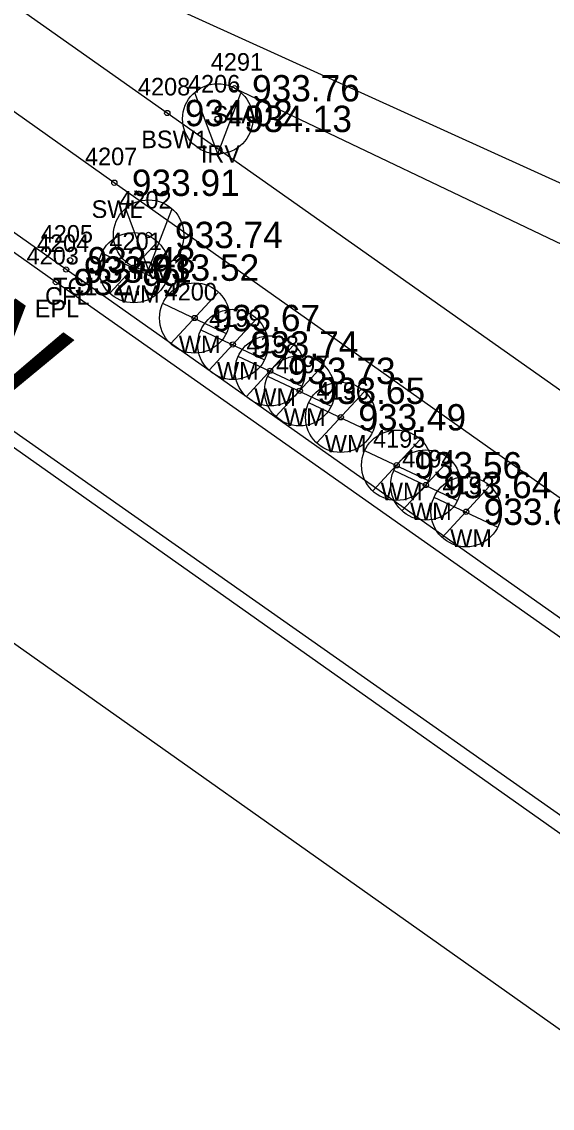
# Model space of a CAD drawing. Extents: x 1575382 to 1578175, y 1099175 to 1101955.
# Drawn here: x 1577254.7 to 1577284.9, y 1101338.2 to 1101400.1 of the extents above; entities that cross this region are included whole.
import ezdxf

# ---------------------------------------------------------------- set-up
doc = ezdxf.new("R2010")
doc.units = 0
for name, color, linetype in [('RD_EX_Bldg', 7, 'Continuous'), ('RD_EX_BldgApp', 7, 'Continuous'), ('RD_EX_Conc', 7, 'Continuous'), ('RD_EX_Conc_txCode', 7, 'Continuous'), ('RD_EX_Misc_txCode', 7, 'Continuous'), ('RD_EX_Road', 7, 'Continuous'), ('RD_EX_Road_txCode', 7, 'Continuous'), ('RD_EX_TX_Conc_ELEV', 7, 'Continuous'), ('RD_EX_TX_Misc_ELEV', 7, 'Continuous'), ('RD_EX_TX_Road_ELEV', 7, 'Continuous'), ('RD_EX_TX_UT_ELEV', 7, 'Continuous'), ('RD_EX_TX_VEG_ELEV', 7, 'Continuous'), ('RD_EX_UT', 7, 'Continuous'), ('RD_EX_UT_txCode', 7, 'Continuous'), ('RD_EX_VEG', 7, 'Continuous'), ('RD_EX_VEG_txCode', 7, 'Continuous'), ('RD_HC_Cl', 7, 'Continuous'), ('RD_HC_Data', 7, 'Continuous'), ('RD_SMD_Locator', 7, 'Continuous')]:
    doc.layers.add(name, color=color, linetype=linetype)

msp = doc.modelspace()

# ---------------------------------------------------------------- linework, layer by layer
at = {"layer": 'RD_EX_Bldg'}
msp.add_lwpolyline([(1577241.109, 1101410.992), (1577311.945, 1101378.805), (1577394.954, 1101563.591), (1577324.118, 1101595.777), (1577241.109, 1101410.992)], dxfattribs=at)
at = {"layer": 'RD_EX_BldgApp'}
for p, q in [((1577265.827, 1101392.566), (1577264.524, 1101396.049)), ((1577265.827, 1101392.566), (1577267.15, 1101396.012)), ((1577261.895, 1101385.958), (1577260.591, 1101389.441)), ((1577261.895, 1101385.958), (1577263.217, 1101389.403))]:
    msp.add_line(p, q, dxfattribs=at)
for centre, radius in [((1577265.827, 1101394.559), 2), ((1577265.827, 1101394.559), 0.15), ((1577261.895, 1101387.951), 2), ((1577261.895, 1101387.951), 0.15)]:
    msp.add_circle(centre, radius, dxfattribs=at)
at = {"layer": 'RD_EX_Conc'}
for points in [[(1577326.739, 1101405.232), (1577316.348, 1101381.047), (1577314.702, 1101377.446), (1577312.765, 1101373.034), (1577307.574, 1101368.224), (1577302.647, 1101367.838), (1577295.881, 1101371.65), (1577262.958, 1101394.891), (1577234.439, 1101415.011), (1577222.087, 1101423.725), (1577202.935, 1101437.614), (1577200.917, 1101438.921), (1577194.112, 1101443.955), (1577177.581, 1101455.534), (1577173.583, 1101458.393), (1577156.819, 1101470.205), (1577152.82, 1101472.9), (1577143.368, 1101479.788), (1577139.034, 1101482.935)], [(1577305.91, 1101358.397), (1577259.945, 1101390.922), (1577231.605, 1101411.039), (1577219.425, 1101419.77), (1577221.243, 1101412.218)], [(1577306.229, 1101358.147), (1577304.05, 1101352.897), (1577257.209, 1101385.982), (1577216.103, 1101415.107)]]:
    msp.add_lwpolyline(points, dxfattribs=at)
at = {"layer": 'RD_EX_Road'}
for points in [[(1577350.994, 1101394.654), (1577333.617, 1101354.382), (1577330.309, 1101348.321), (1577323.84, 1101345.402), (1577317.431, 1101344.498), (1577311.613, 1101346.411), (1577303.255, 1101352.397), (1577256.622, 1101385.271), (1577215.6, 1101414.322), (1577175.525, 1101442.942), (1577135.202, 1101471.708)], [(1577206.431, 1101064.716), (1577225.664, 1101106.496), (1577239.191, 1101137.5), (1577259.229, 1101183.338), (1577279.151, 1101229.325), (1577299.025, 1101275.068), (1577314.414, 1101310.726), (1577314.923, 1101317.44), (1577309.623, 1101326.254), (1577295.813, 1101333.968), (1577286.609, 1101341.784), (1577246.231, 1101370.35), (1577205.316, 1101399.097), (1577164.905, 1101427.552), (1577123.312, 1101456.71)]]:
    msp.add_lwpolyline(points, dxfattribs=at)
at = {"layer": 'RD_EX_UT'}
for p, q in [((1577259.699, 1101384.632), (1577262.366, 1101387.528)), ((1577259.217, 1101386.927), (1577262.848, 1101385.214)), ((1577263.163, 1101381.764), (1577265.83, 1101384.661)), ((1577262.682, 1101384.06), (1577266.312, 1101382.347)), ((1577265.338, 1101380.262), (1577268.005, 1101383.159)), ((1577264.857, 1101382.557), (1577268.487, 1101380.845)), ((1577267.46, 1101378.759), (1577270.127, 1101381.656)), ((1577266.978, 1101381.055), (1577270.609, 1101379.342)), ((1577269.139, 1101377.623), (1577271.806, 1101380.52)), ((1577268.658, 1101379.919), (1577272.288, 1101378.206)), ((1577271.471, 1101376.115), (1577274.139, 1101379.012)), ((1577270.99, 1101378.41), (1577274.621, 1101376.698)), ((1577274.656, 1101373.385), (1577277.323, 1101376.282)), ((1577274.174, 1101375.681), (1577277.805, 1101373.968)), ((1577276.318, 1101372.26), (1577278.985, 1101375.157)), ((1577275.836, 1101374.555), (1577279.467, 1101372.843)), ((1577278.604, 1101370.739), (1577281.272, 1101373.635)), ((1577278.123, 1101373.034), (1577281.754, 1101371.321))]:
    msp.add_line(p, q, dxfattribs=at)
msp.add_lwpolyline([(1577014.29, 1101543.334), (1577198.946, 1101415.644), (1577337.019, 1101318.587)], dxfattribs=at)
for centre in [(1577261.051, 1101386.09), (1577264.515, 1101383.223), (1577266.69, 1101381.72), (1577268.812, 1101380.218), (1577270.491, 1101379.082), (1577272.823, 1101377.573), (1577276.008, 1101374.843), (1577277.67, 1101373.718), (1577279.957, 1101372.197)]:
    msp.add_circle(centre, 2, dxfattribs=at)
at = {"layer": 'RD_EX_VEG'}
msp.add_line((1577266.779, 1101396.301), (1577292.768, 1101383.89), dxfattribs=at)
at = {"layer": 'RD_HC_Cl'}
msp.add_line((1577333.443, 1101319.831), (1577129.246, 1101464.193), dxfattribs=at)
at = {"layer": 'RD_SMD_Locator'}
for centre in [(1577266.779, 1101396.301), (1577262.958, 1101394.891), (1577259.945, 1101390.922), (1577257.426, 1101386.513), (1577261.051, 1101386.09), (1577257.209, 1101385.982), (1577256.622, 1101385.271), (1577264.515, 1101383.223), (1577266.69, 1101381.72), (1577268.812, 1101380.218), (1577270.491, 1101379.082), (1577272.823, 1101377.573), (1577276.008, 1101374.843), (1577277.67, 1101373.718), (1577279.957, 1101372.197)]:
    msp.add_circle(centre, 0.15, dxfattribs=at)

# ---------------------------------------------------------------- texts
at = {"layer": 'RD_EX_Conc_txCode'}
for s, p in [('4208', (1577261.288, 1101395.891)), ('BSW1', (1577261.477, 1101392.891)), ('4207', (1577258.276, 1101391.922)), ('SWL', (1577258.653, 1101388.922)), ('4204', (1577255.54, 1101386.982)), ('4205', (1577255.757, 1101387.513)), ('TC1', (1577256.465, 1101384.513)), ('CFL', (1577256.004, 1101383.982))]:
    msp.add_text(s, height=1, dxfattribs=at).set_placement(p)
at = {"layer": 'RD_EX_Misc_txCode'}
for s, p in [('4206', (1577264.134, 1101396.059)), ('IRV', (1577264.867, 1101392.059)), ('4202', (1577260.225, 1101389.451)), ('IRV', (1577260.934, 1101385.451))]:
    msp.add_text(s, height=1, dxfattribs=at).set_placement(p)
at = {"layer": 'RD_EX_Road_txCode'}
for s, p in [('4203', (1577254.953, 1101386.271)), ('EPL', (1577255.418, 1101383.271))]:
    msp.add_text(s, height=1, dxfattribs=at).set_placement(p)
at = {"layer": 'RD_EX_TX_Conc_ELEV'}
for s, p in [('934.02', (1577263.958, 1101394.141)), ('933.91', (1577260.945, 1101390.172)), ('933.01', (1577258.209, 1101385.232)), ('933.48', (1577258.426, 1101385.763))]:
    msp.add_text(s, height=1.5, dxfattribs=at).set_placement(p)
at = {"layer": 'RD_EX_TX_Misc_ELEV'}
for s, p in [('934.13', (1577267.327, 1101393.809)), ('933.74', (1577263.395, 1101387.201))]:
    msp.add_text(s, height=1.5, dxfattribs=at).set_placement(p)
at = {"layer": 'RD_EX_TX_Road_ELEV'}
msp.add_text('932.99', height=1.5, dxfattribs=at).set_placement((1577257.622, 1101384.521))
at = {"layer": 'RD_EX_TX_UT_ELEV'}
for s, p in [('933.52', (1577262.051, 1101385.34)), ('933.67', (1577265.515, 1101382.473)), ('933.74', (1577267.69, 1101380.97)), ('933.73', (1577269.812, 1101379.468)), ('933.65', (1577271.491, 1101378.332)), ('933.49', (1577273.823, 1101376.823)), ('933.56', (1577277.008, 1101374.093)), ('933.64', (1577278.67, 1101372.968)), ('933.63', (1577280.957, 1101371.447))]:
    msp.add_text(s, height=1.5, dxfattribs=at).set_placement(p)
at = {"layer": 'RD_EX_TX_VEG_ELEV'}
msp.add_text('933.76', height=1.5, dxfattribs=at).set_placement((1577267.779, 1101395.551))
at = {"layer": 'RD_EX_UT_txCode'}
for s, p in [('4201', (1577259.665, 1101387.09)), ('WM', (1577260.145, 1101384.09)), ('4200', (1577262.806, 1101384.223)), ('4199', (1577265.344, 1101382.72)), ('WM', (1577263.61, 1101381.223)), ('4198', (1577267.465, 1101381.218)), ('WM', (1577265.784, 1101379.72)), ('4197', (1577269.145, 1101380.082)), ('4196', (1577271.453, 1101378.573)), ('WM', (1577267.906, 1101378.218)), ('WM', (1577269.585, 1101377.082)), ('WM', (1577271.918, 1101375.573)), ('4195', (1577274.661, 1101375.843)), ('4194', (1577276.323, 1101374.718)), ('WM', (1577275.102, 1101372.843)), ('4193', (1577278.61, 1101373.197)), ('WM', (1577276.764, 1101371.718)), ('WM', (1577279.051, 1101370.197))]:
    msp.add_text(s, height=1, dxfattribs=at).set_placement(p)
at = {"layer": 'RD_EX_VEG_txCode'}
for s, p in [('4291', (1577265.432, 1101397.301)), ('SLA', (1577265.535, 1101394.301))]:
    msp.add_text(s, height=1, dxfattribs=at).set_placement(p)
at = {"layer": 'RD_HC_Data'}
msp.add_text('N 54%%d 44\' 26" W', height=6, rotation=324.74061, dxfattribs=at).set_placement((1577207.985, 1101409.752))

doc.saveas('drawing.dxf')
